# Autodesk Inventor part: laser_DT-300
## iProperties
Shininess: 64.0
Length Units: 11269
Angle Units: 11279
Time Units: 11290
Mass Units: 11283
Length Display Precision: 3
Angle Display Precision: 2
Compacted: True
Part Number: laser_DT-300
Document SubType Name: Modeling
Created: 2004-08
Designer: John Blackburn
Manufacturer: Standard
Standards Organization: Custom
Density: 0.0
Volumn: 0.0
Area: 0.0
PropertySet Name: Model Information
Control State: 0
Master: False
Checked Out: False
Author: John Blackburn
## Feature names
1. Extrusion1
2. Extrusion2
3. Extrusion3
4. Hole1
5. Hole2
